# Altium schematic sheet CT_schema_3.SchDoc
size 206 x 169 mm
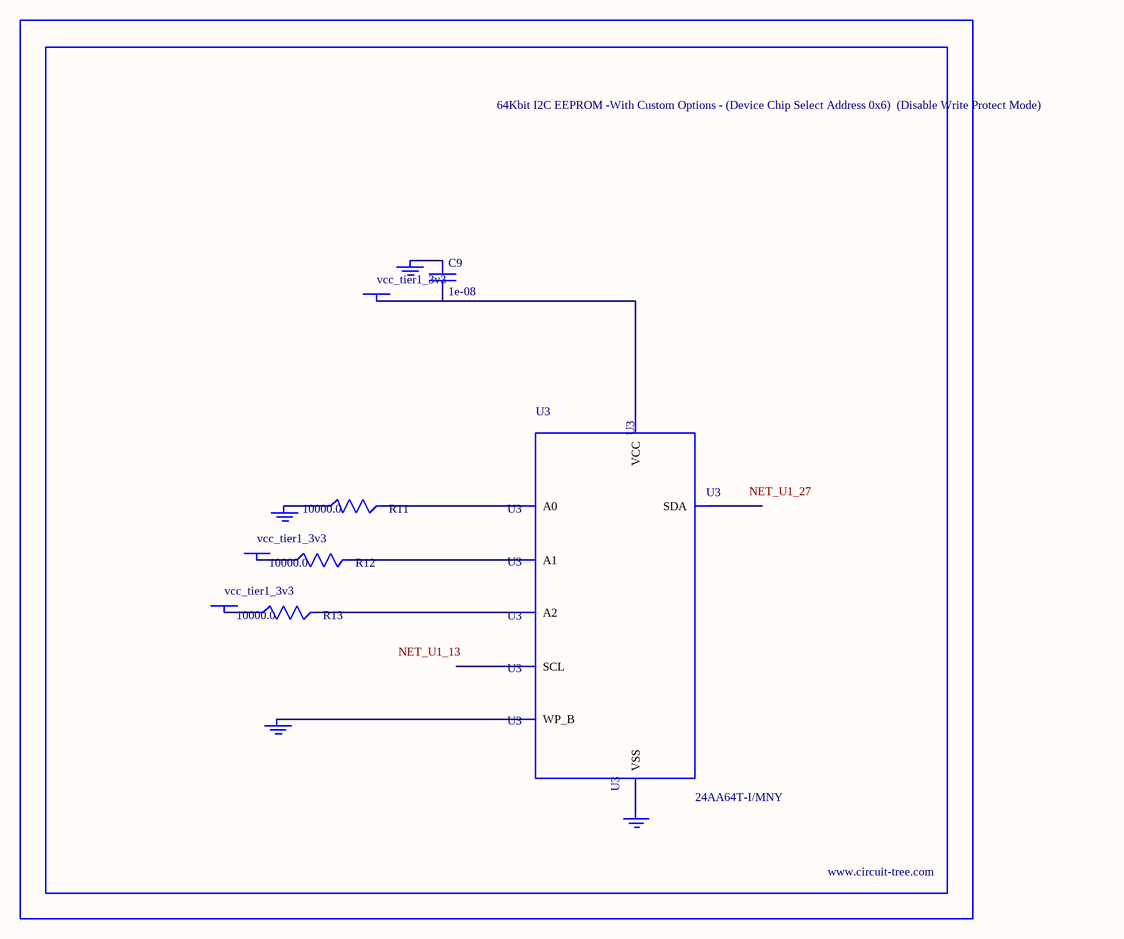
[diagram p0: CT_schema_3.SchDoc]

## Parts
BORDER2  (no value)
C9  1e-08  [C0402]
GND_INSTANCE_2_0  (no value)
GND_INSTANCE_2_1  (no value)
GND_INSTANCE_2_2  (no value)
GND_INSTANCE_2_3  (no value)
POWER_INSTANCE_2_0  vcc_tier1_3v3
POWER_INSTANCE_2_1  vcc_tier1_3v3
POWER_INSTANCE_2_2  vcc_tier1_3v3
R11  10000.0  [R0603]
R12  10000.0  [R0603]
R13  10000.0  [R0603]
U3  24AA64T-I/MNY  [TDFN-8/6MM]

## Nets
NetC9_1: C9.1 GND_INSTANCE_2_2.0(GND)
NetC9_2: C9.2 POWER_INSTANCE_2_2.0(PWR) U3.8(VCC)
NetGND_INSTANCE_2_0_0: GND_INSTANCE_2_0.0(GND) R11.1
NetGND_INSTANCE_2_1_0: GND_INSTANCE_2_1.0(GND) U3.7(WP_B)
NetGND_INSTANCE_2_3_0: GND_INSTANCE_2_3.0(GND) U3.4(VSS)
NetPOWER_INSTANCE_2_0_0: POWER_INSTANCE_2_0.0(PWR) R12.1
NetPOWER_INSTANCE_2_1_0: POWER_INSTANCE_2_1.0(PWR) R13.1
NetR11_2: R11.2 U3.1(A0)
NetR12_2: R12.2 U3.2(A1)
NetR13_2: R13.2 U3.3(A2)

Not connected (* = marked no-connect by the designer): U3 5(SDA) 6(SCL)

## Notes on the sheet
- Labels drawn without touching a wire or pin: NET_U1_13, NET_U1_27

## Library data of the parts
BORDER2 = BORDER_PAGE2
C9 = C0402C103K3RAC
GND_INSTANCE_2_0-GND_INSTANCE_2_3 = GND
POWER_INSTANCE_2_0-POWER_INSTANCE_2_2 = PWR
R11-R13 = RC0603JR-0710KL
